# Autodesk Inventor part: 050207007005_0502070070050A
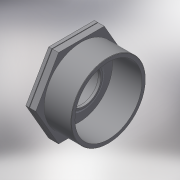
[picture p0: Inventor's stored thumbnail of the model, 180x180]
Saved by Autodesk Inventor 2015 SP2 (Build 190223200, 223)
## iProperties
Created: 2017-05
Part Number: 050207007005_0502070070050A
Material: Generic
Description: PLASSON REDUCING BUSHING 3/4"-1/2"
Document SubType Name: Modeling
Designer: KIM
Density: 1 g/cm^3
Appearance: Default
Author: KIM
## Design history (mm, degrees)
derived "050207.ipt"
feature "Solid1::050207.ipt"
tag "TaggingFeature1"
body "Solid1"
other parameters: "d1" = 26.441, "d2" = 27, "d5" = 17, "d8" = 0.3, "d12" = 0, "d19" = 0, "d30" = 7.5, "d31" = 3.75, "d33" = 18.631, "d34" = 23.7969, "d36" = 1.35, "d37" = 22.3572, "d38" = 19.8, "d39" = 16.7679, "d40" = 1.7, "d41" = 0, "R_" = 26.441, "E_" = 27, "l_2" = 17, "Rp_" = 18.631
